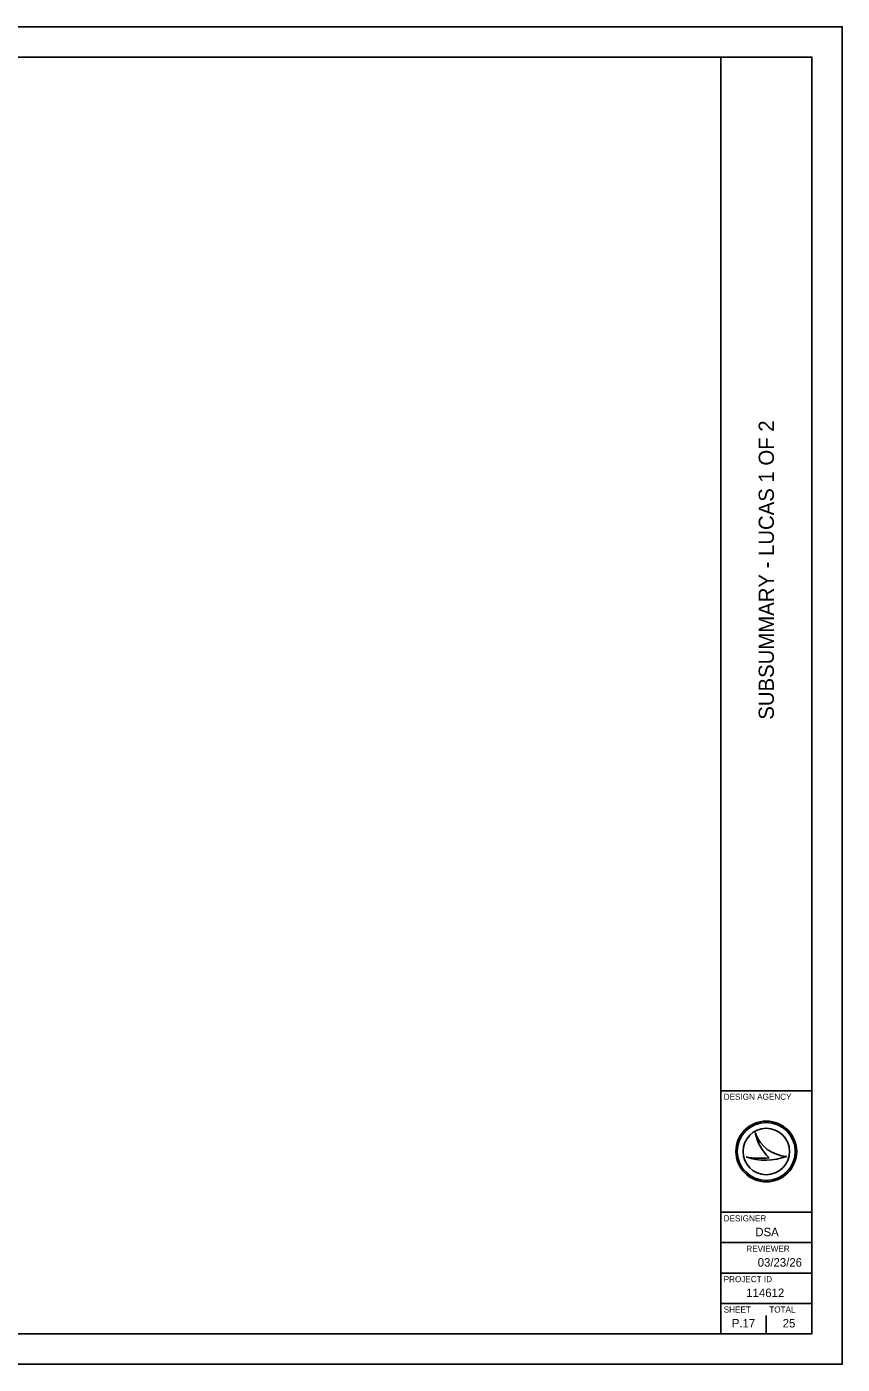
# Model space of a CAD drawing. Extents: x 0 to 34, y 0 to 22.
# Drawn here: x 20.58 to 34, y 0 to 22 of the extents above; entities that cross this region are included whole.
import ezdxf

# ---------------------------------------------------------------- set-up
doc = ezdxf.new("R2010")
doc.units = 0
for name, color, linetype in [('SH_Border', 7, 'Continuous'), ('SH_Cut_Line', 7, 'Continuous'), ('SH_Data', 7, 'Continuous')]:
    doc.layers.add(name, color=color, linetype=linetype)

msp = doc.modelspace()

# ---------------------------------------------------------------- linework, layer by layer
at = {"layer": 'SH_Border'}
for p, q in [((32, 0.5), (32, 21.5)), ((32, 4.5), (33.5, 4.5)), ((32, 2.5), (33.5, 2.5)), ((32, 2), (33.5, 2)), ((32, 1.5), (33.5, 1.5)), ((32, 1), (33.5, 1))]:
    msp.add_line(p, q, dxfattribs=at)
msp.add_lwpolyline([(1.5, 21.5), (33.5, 21.5), (33.5, 0.5), (1.5, 0.5)], close=True, dxfattribs=at)
at = {"layer": 'SH_Cut_Line'}
msp.add_lwpolyline([(0, 0), (34, 0), (34, 22), (0, 22)], close=True, dxfattribs=at)
at = {"layer": 'SH_Data'}
for p, q in [((32.567, 3.81), (32.567, 3.81)), ((32.417, 3.41), (32.417, 3.41)), ((32.75, 3.5), (32.75, 3.5)), ((33.087, 3.419), (33.087, 3.419)), ((32.375, 0.675), (32.375, 0.675)), ((32.75, 0.5), (32.75, 0.8))]:
    msp.add_line(p, q, dxfattribs=at)
for radius in [0.5, 0.477, 0.477, 0.382]:
    msp.add_circle((32.75, 3.5), radius, dxfattribs=at)
for centre, radius, start, end in [((33.116, 3.998), 0.58, 198.9257, 198.9319), ((33.347, 3.97), 0.796, 191.6379, 191.6421), ((33.116, 3.998), 0.58, 198.9319, 267.1657), ((33.347, 3.97), 0.796, 191.6421, 226.0947), ((32.739, 4.37), 1.013, 251.4576, 290.0832), ((32.648, 4.654), 1.266, 259.4964, 259.4995), ((32.739, 4.37), 1.013, 251.4527, 251.4576), ((32.648, 4.654), 1.266, 259.4995, 276.6672)]:
    msp.add_arc(centre, radius, start, end, dxfattribs=at)

# ---------------------------------------------------------------- texts
msp.add_text('SUBSUMMARY - LUCAS 1 OF 2', height=0.25, rotation=90, dxfattribs=at).set_placement((32.875, 10.602))
for s, height, p in [('DESIGN AGENCY', 0.1, (32.05, 4.35)), ('DESIGNER', 0.1, (32.05, 2.35)), ('DSA', 0.14, (32.57, 2.105)), ('REVIEWER', 0.1, (32.422, 1.85)), ('03/23/26', 0.14, (32.609, 1.605)), ('PROJECT ID', 0.1, (32.05, 1.35)), ('114612', 0.14, (32.421, 1.105)), ('SHEET', 0.1, (32.05, 0.85)), ('TOTAL', 0.1, (32.8, 0.85)), ('P.17', 0.14, (32.183, 0.605)), ('25', 0.14, (33.02, 0.605))]:
    msp.add_text(s, height=height, dxfattribs=at).set_placement(p)

doc.saveas('drawing.dxf')
